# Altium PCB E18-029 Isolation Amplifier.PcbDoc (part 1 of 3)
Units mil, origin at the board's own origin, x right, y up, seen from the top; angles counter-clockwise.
Board outline 5740 x 5970 mil, 4 copper layers (Component Side, V+, V-, Ground), stack 33.234 mil thick; 359 components, 170 nets, 952 pads, 232 vias.
Unrouted connection lines stored in the file: 60.
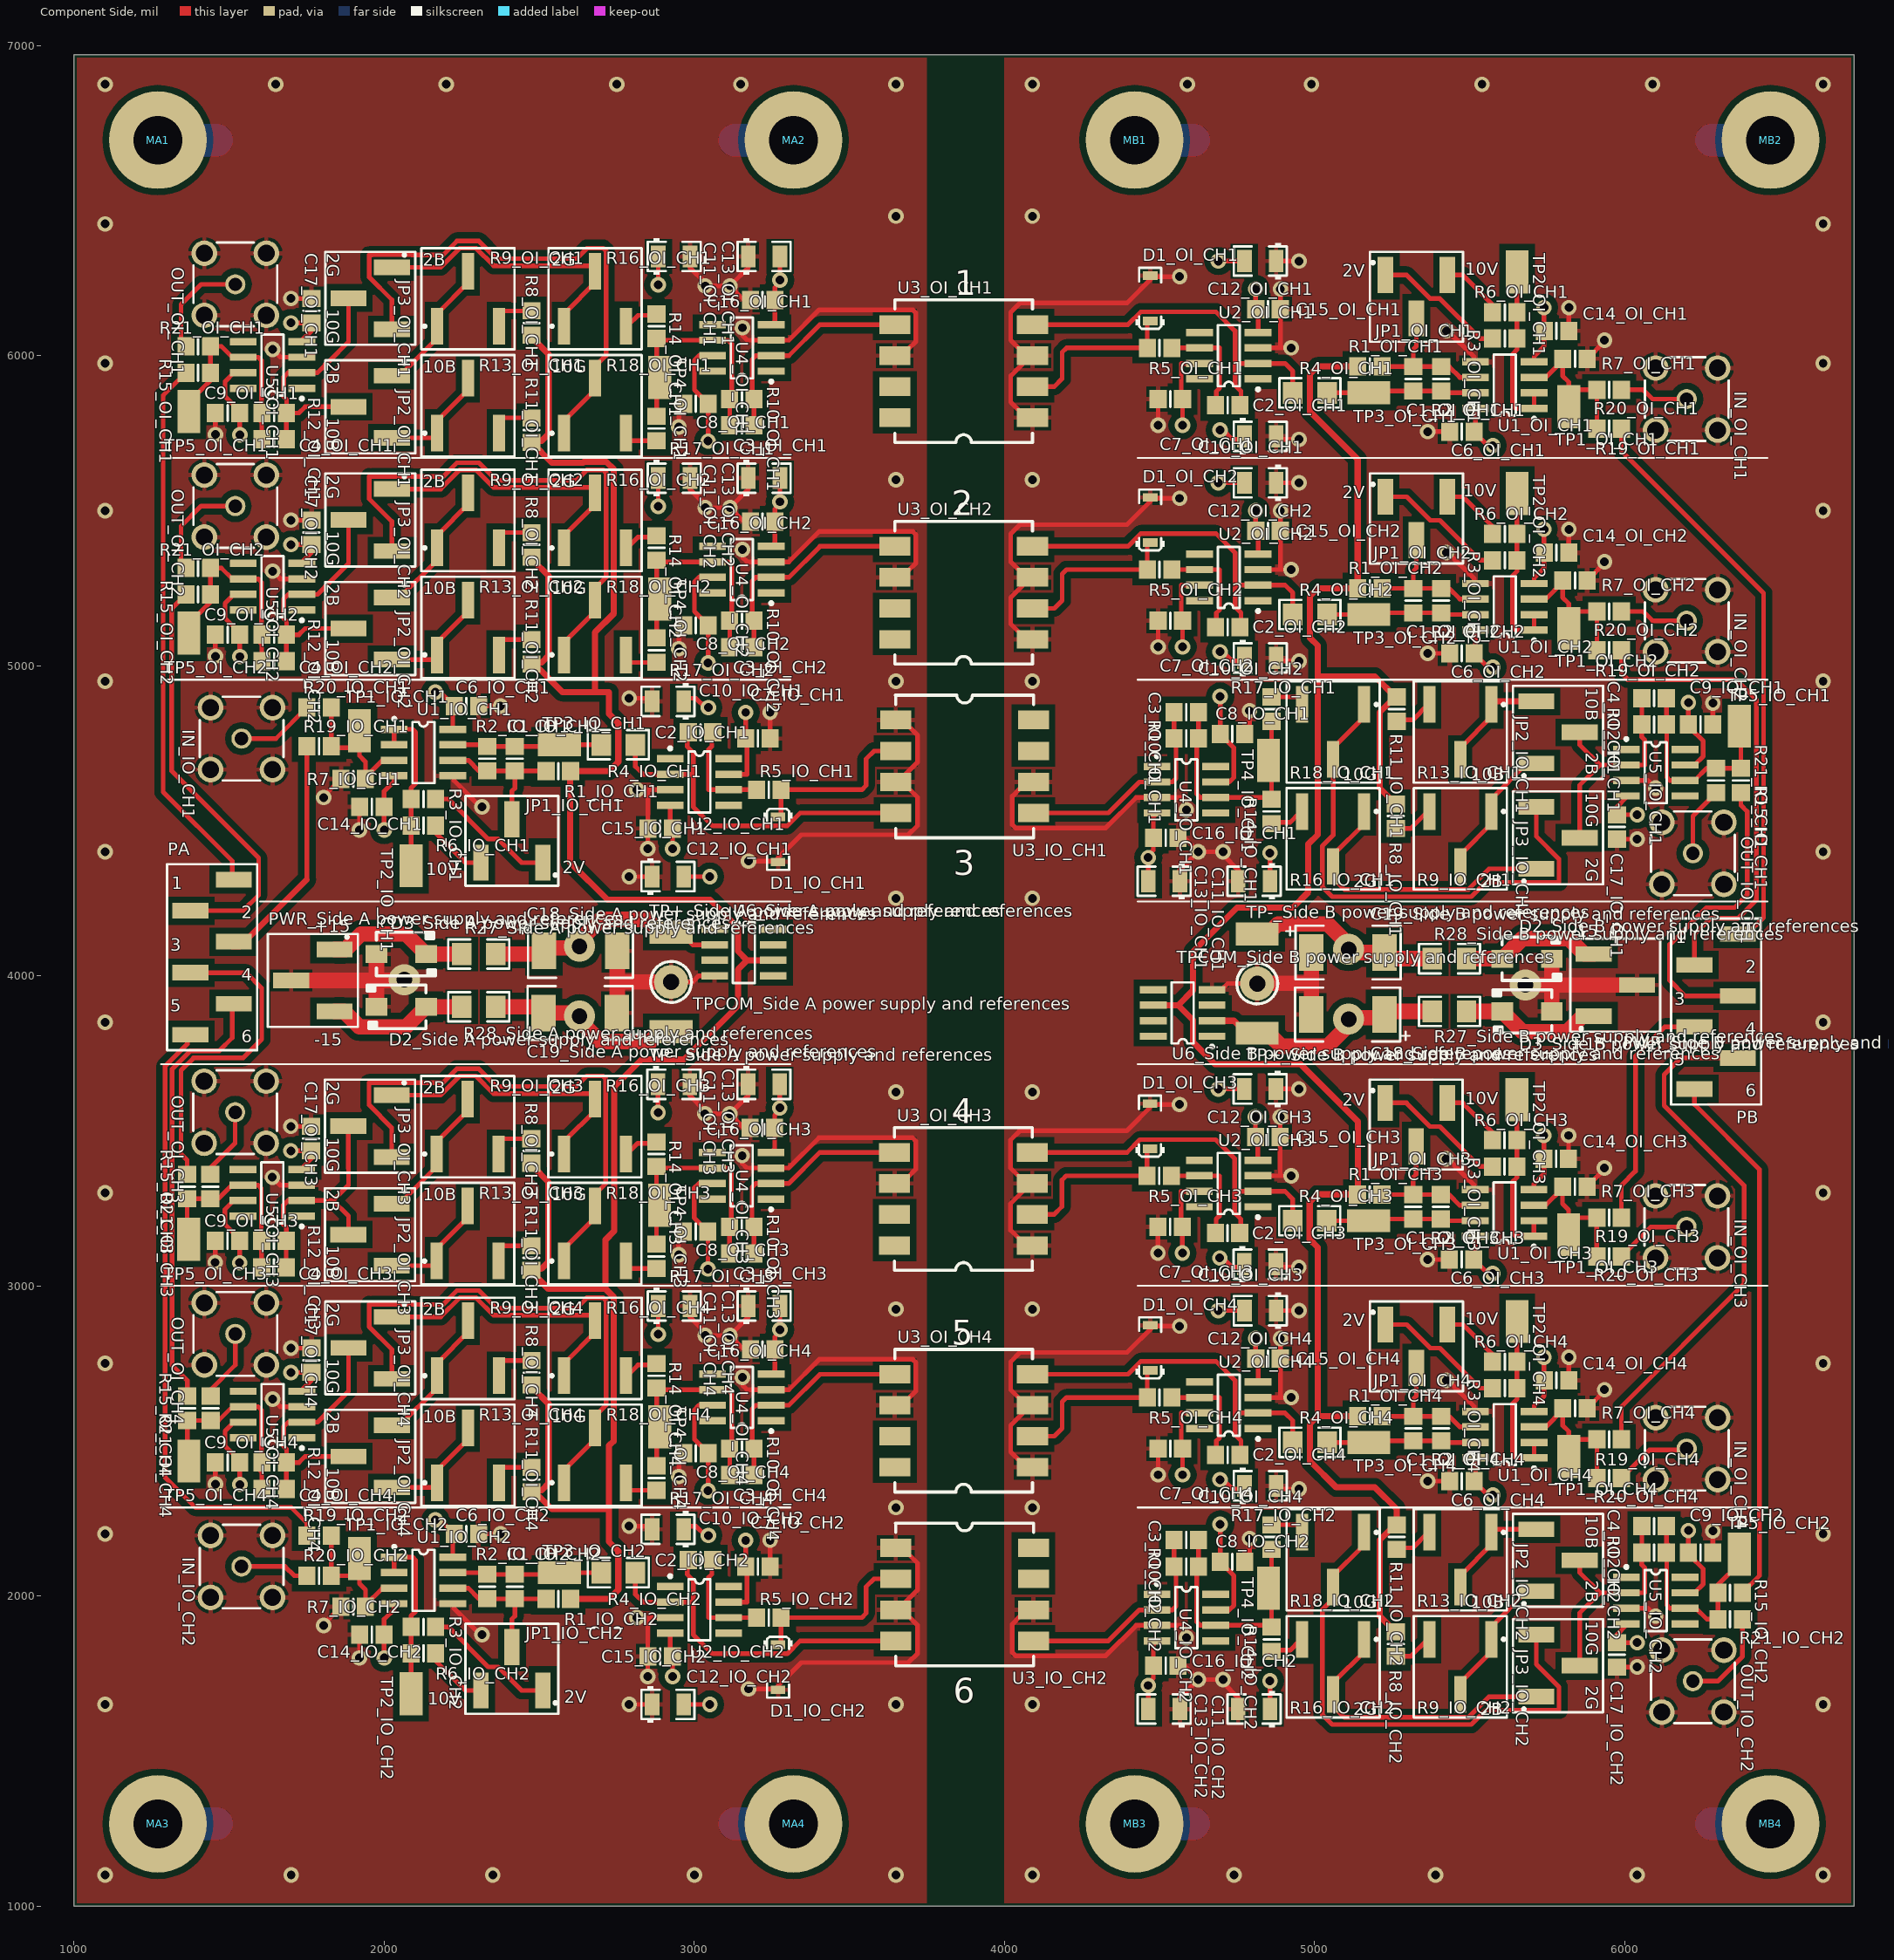
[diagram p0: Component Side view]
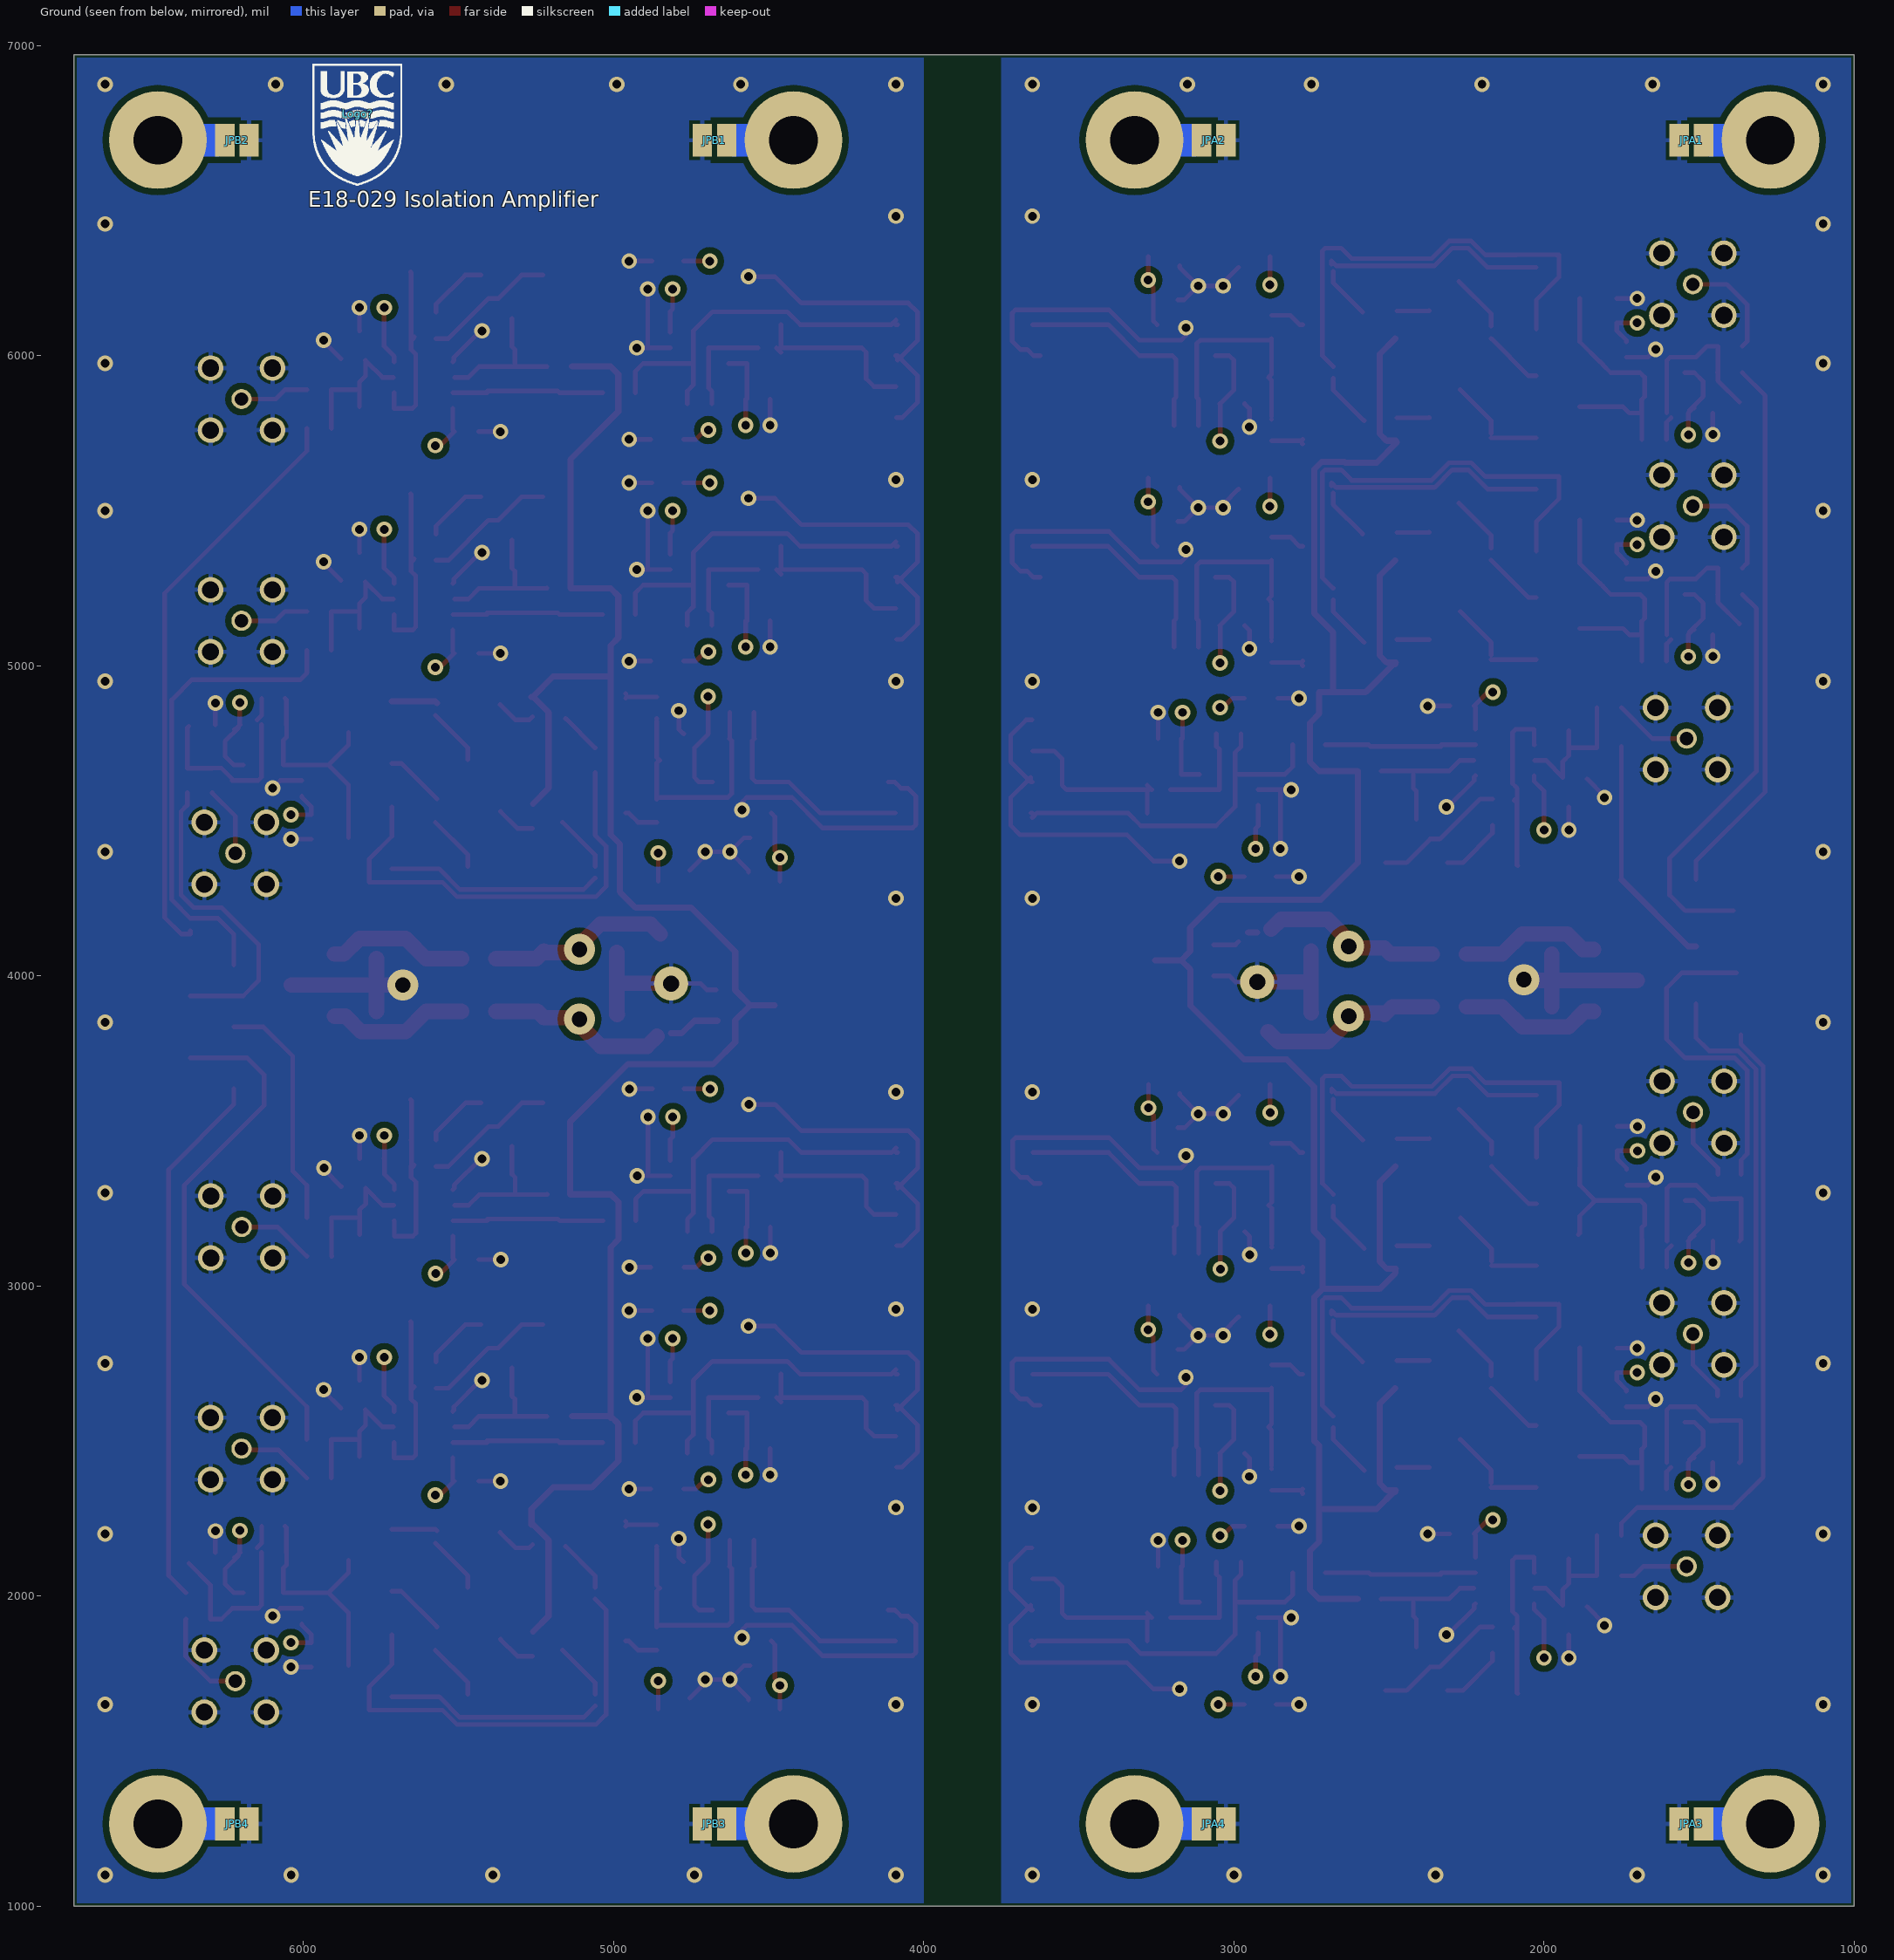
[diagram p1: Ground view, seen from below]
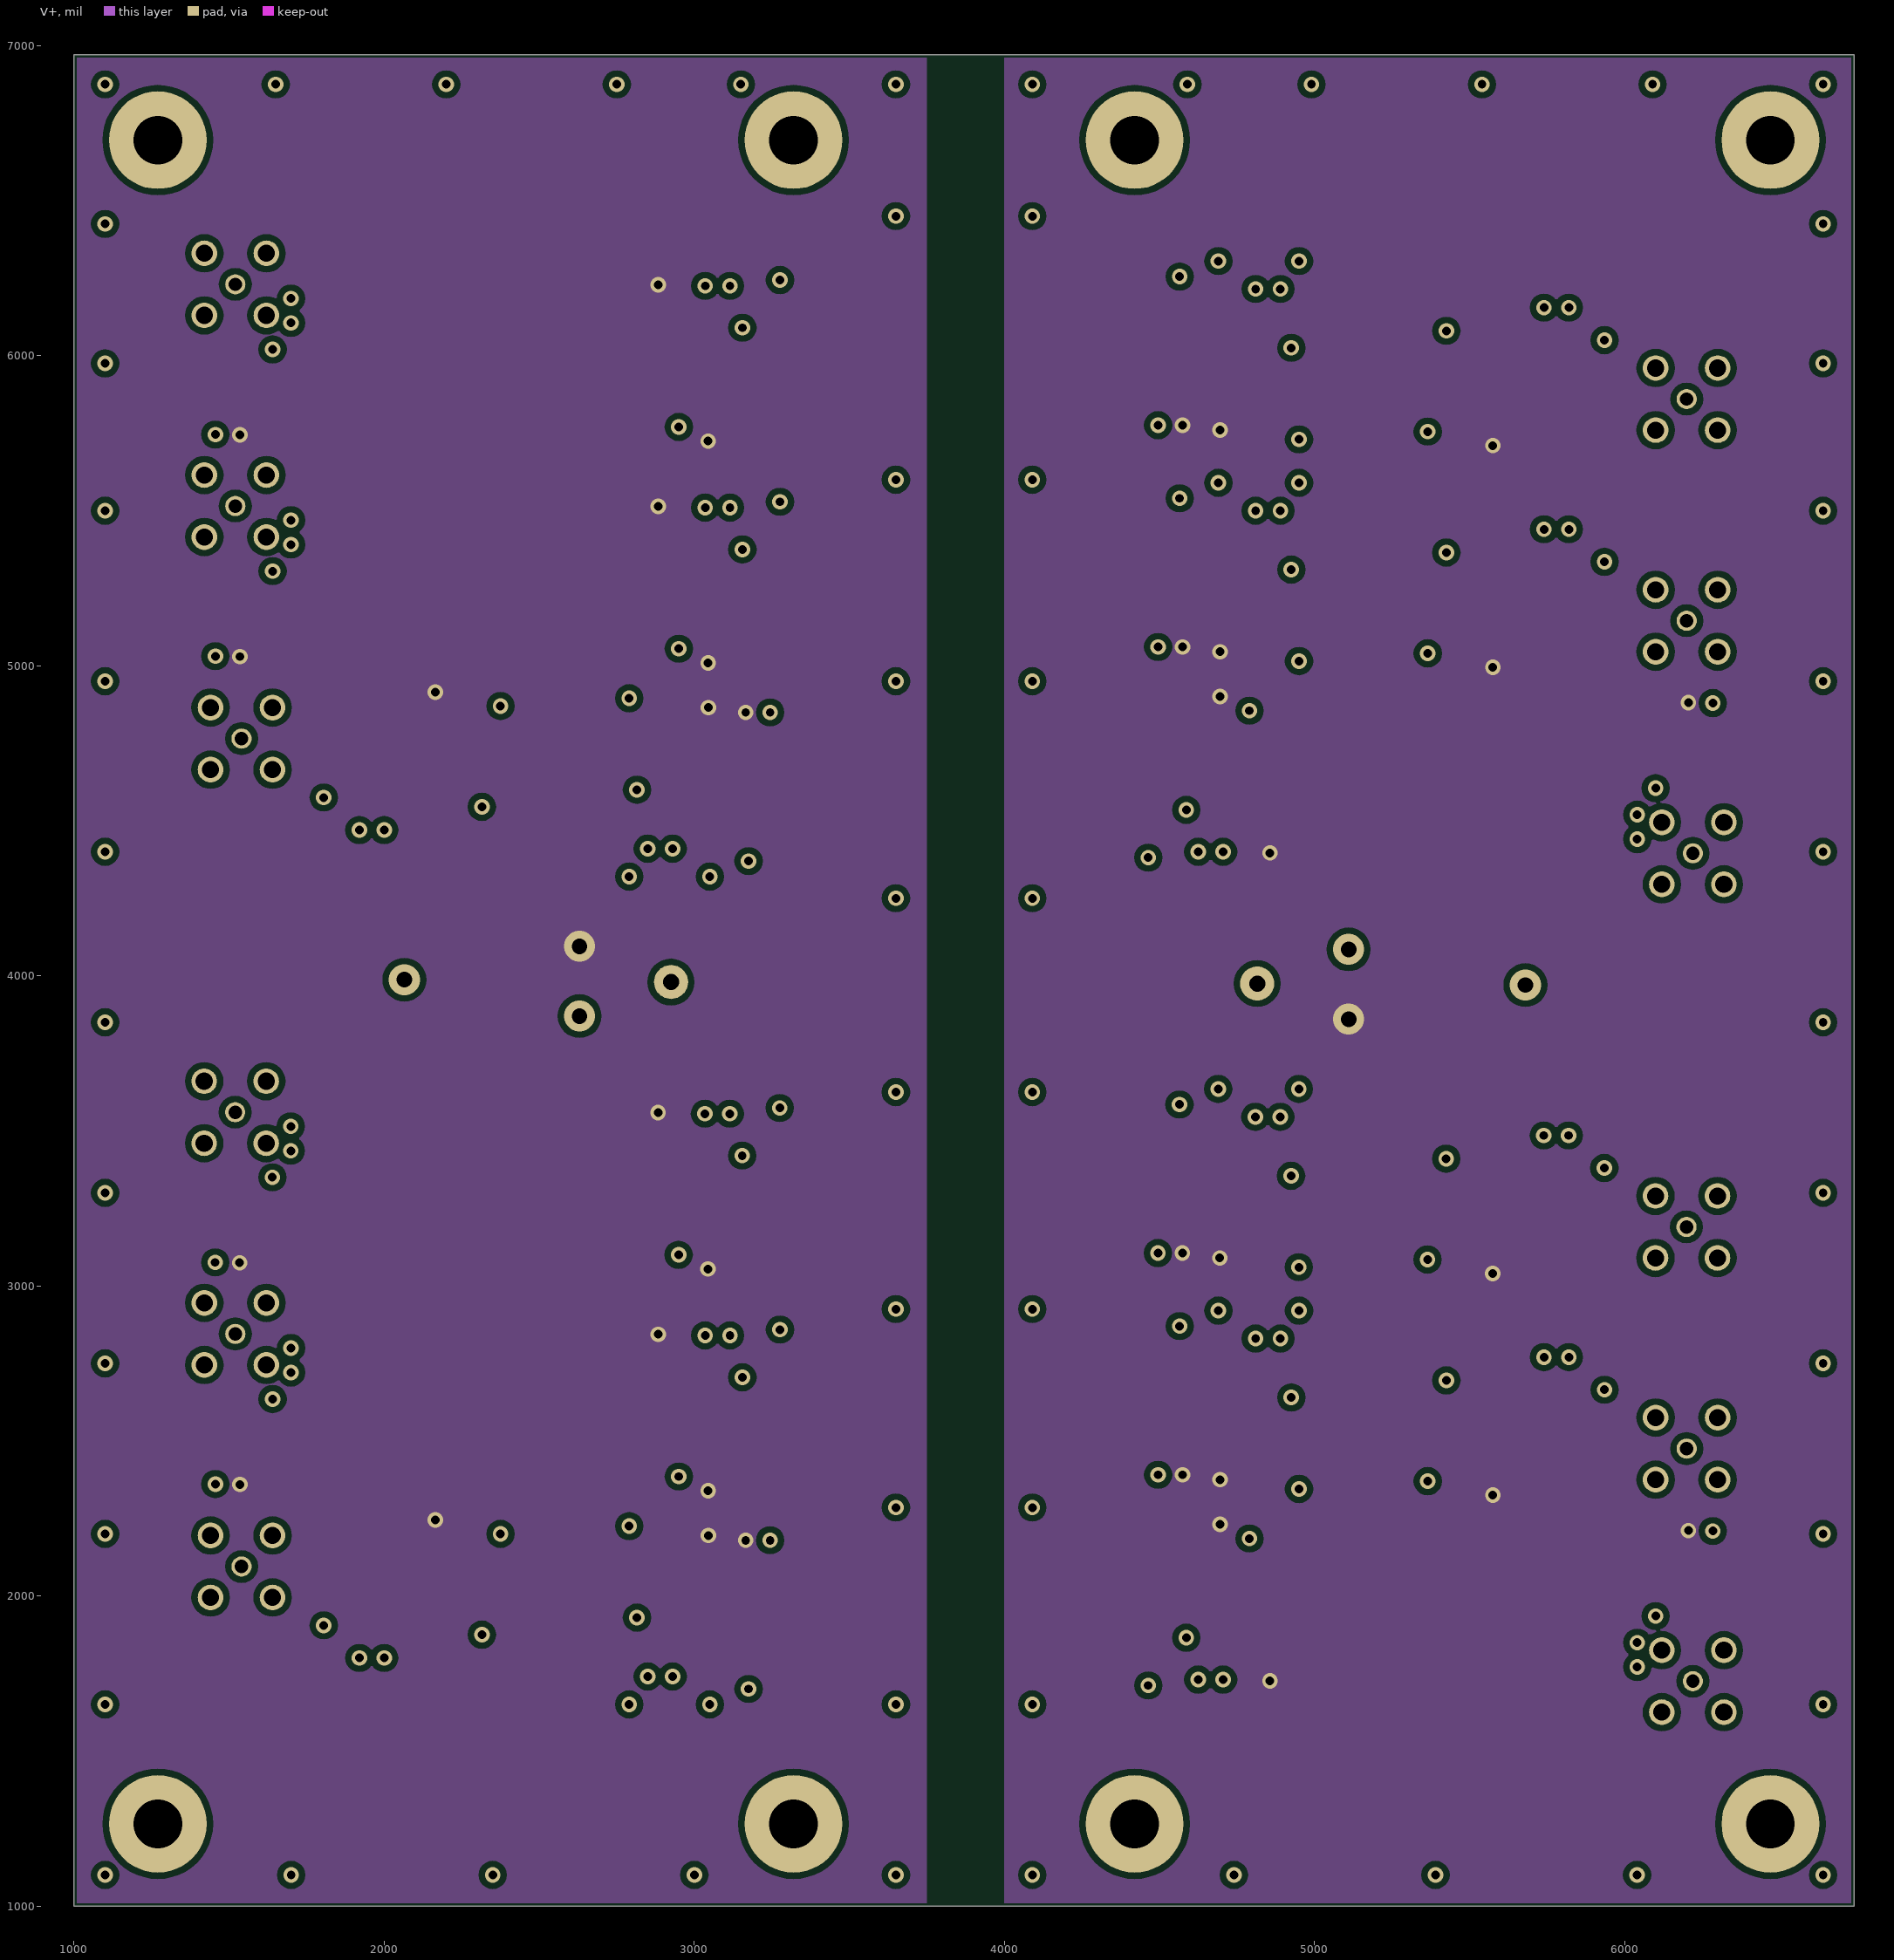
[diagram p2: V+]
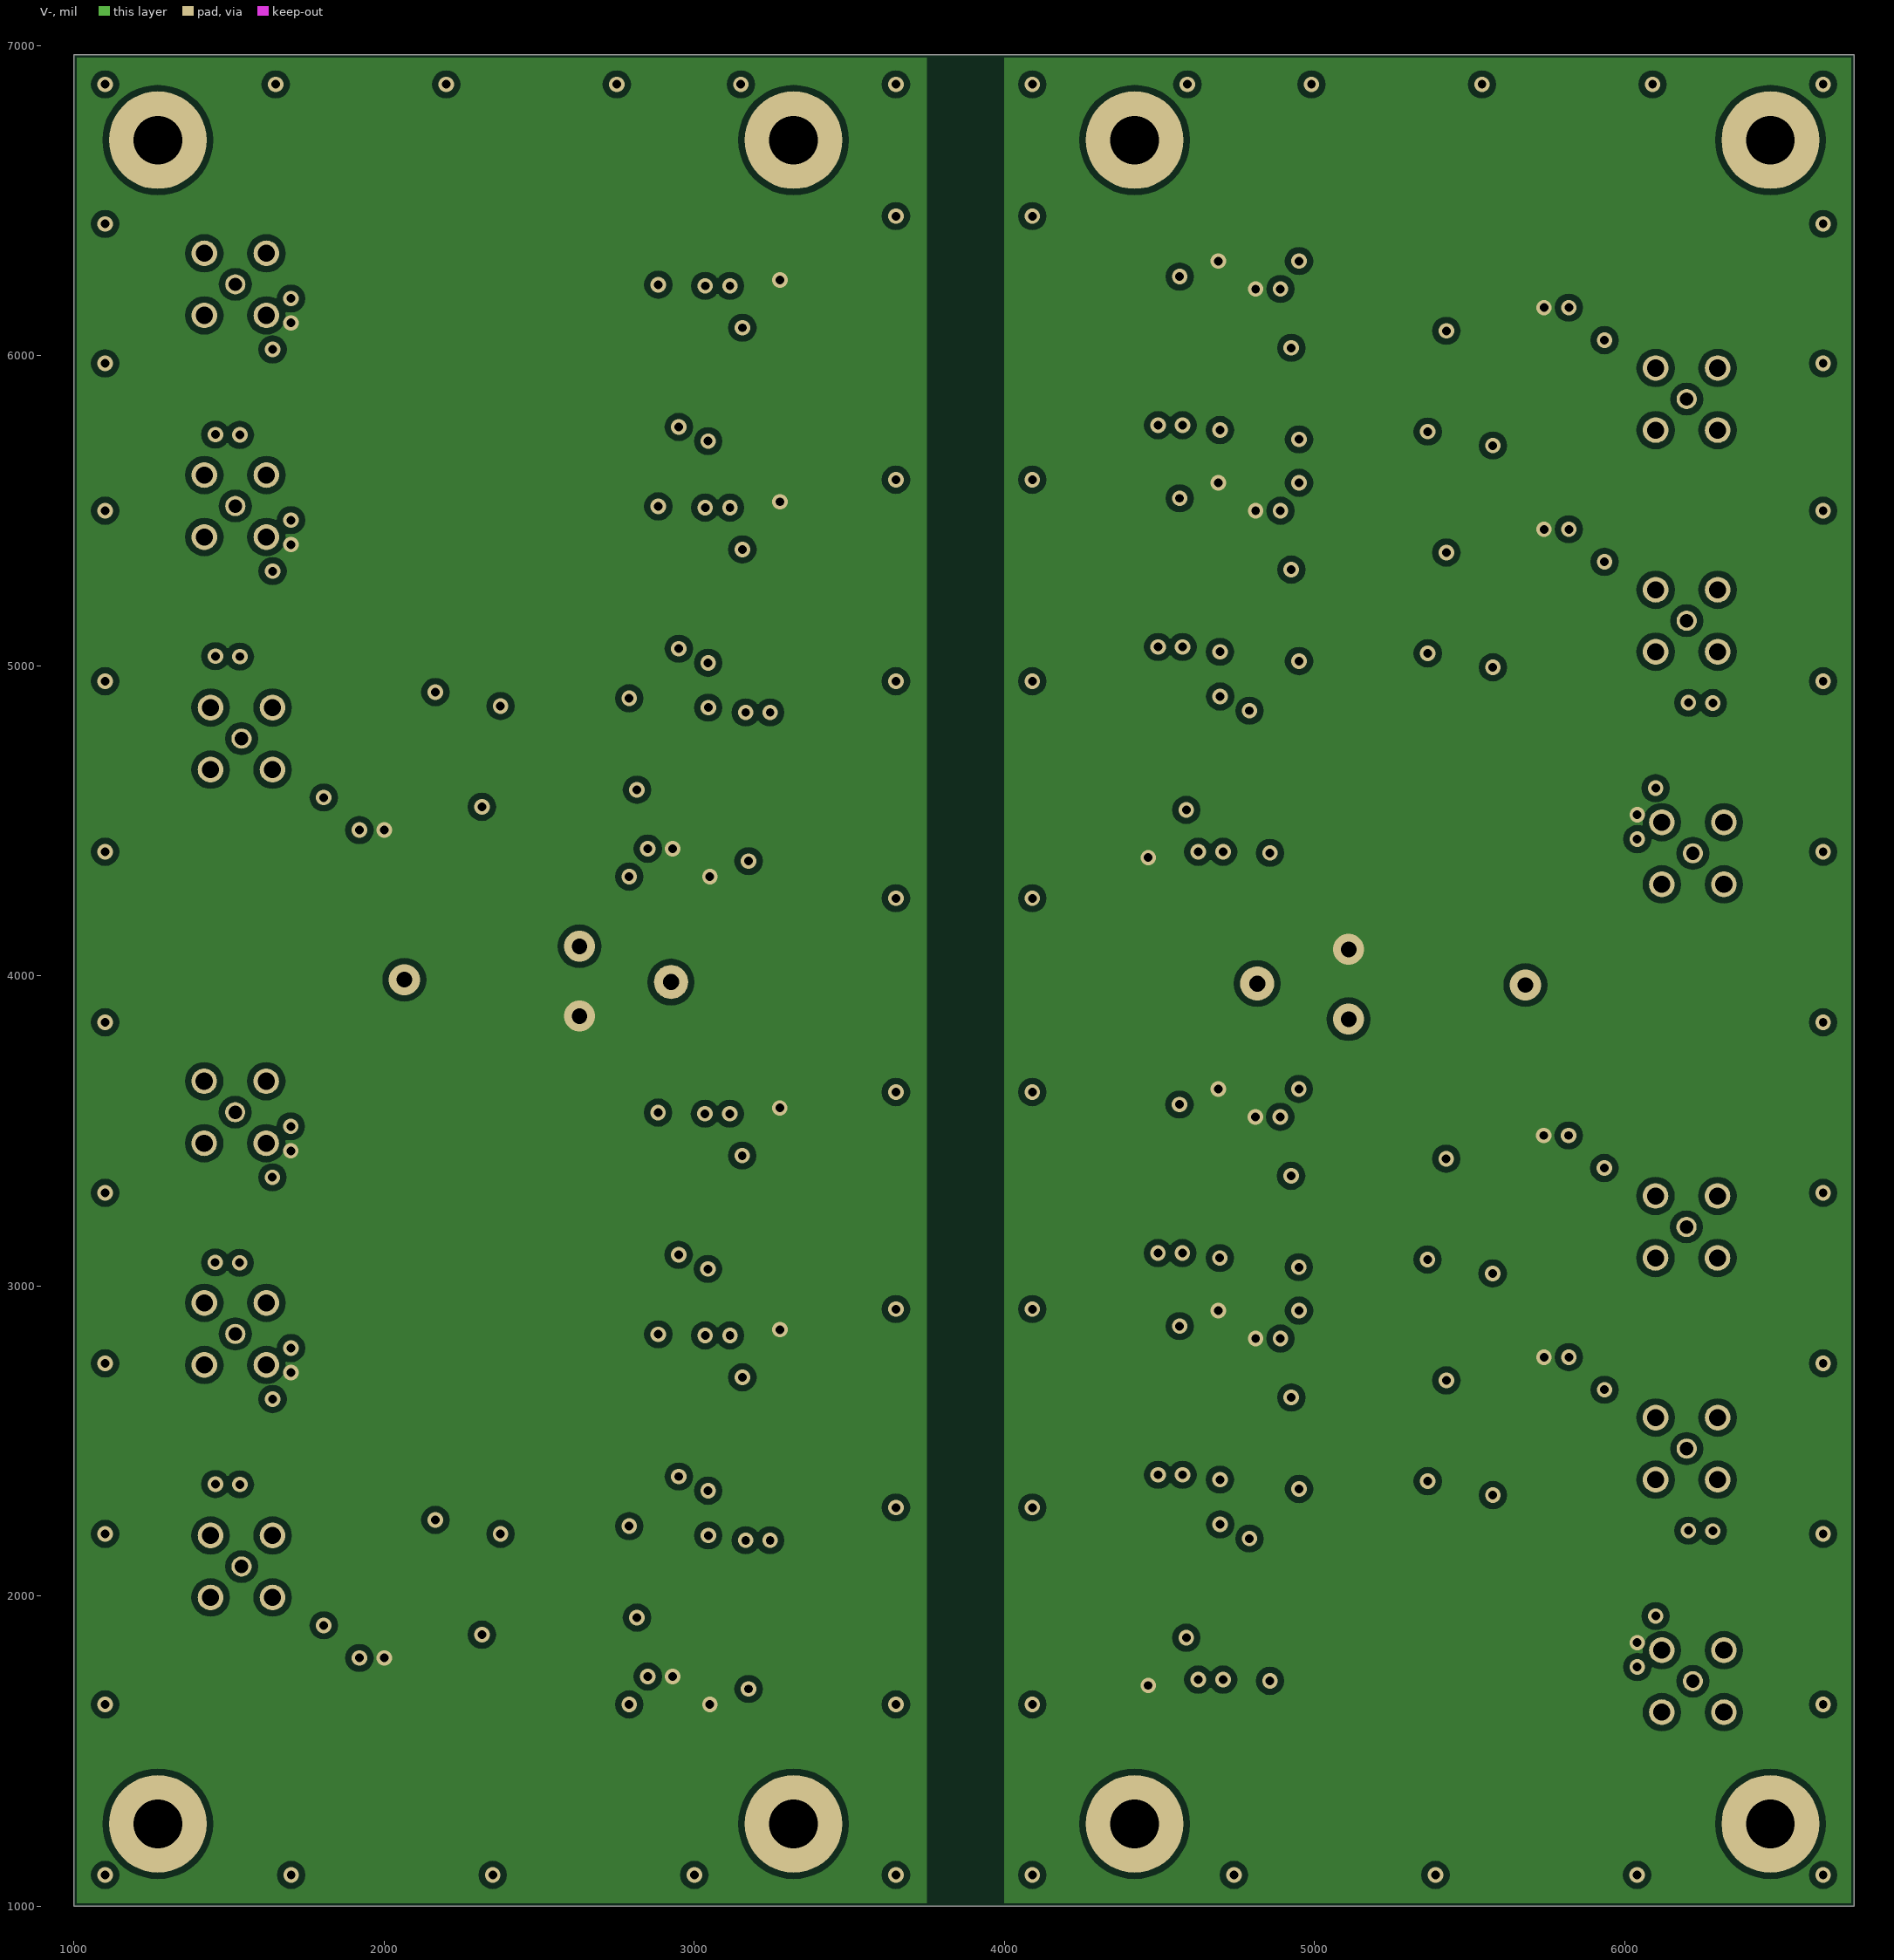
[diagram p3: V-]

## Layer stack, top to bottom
Top Solder: solder mask 0.4, Solder Resist, Dk 3.5
Component Side: signal copper 1.4
Dielectric 1: core 12.6, FR-4, Dk 4.8
V+: signal copper 1.417
Dielectric 4: prepreg 5, Dk 4.2
V-: signal copper 1.417
Dielectric 3: core 10, Dk 4.2
Ground: signal copper 1.4
Bottom Solder: solder mask 0.4, Solder Resist, Dk 3.5

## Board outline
1000,1000 1000,6970 6740,6970 6740,1000

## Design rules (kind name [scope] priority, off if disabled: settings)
AcuteAngle [All] p1: minimum=3.00000000000000E+0001 checktracksonly=FALSE
Clearance Polygon_Pour [InPolygon] p1: gap=20 ignorepadtopadclearanceinfootprint=FALSE except(0: Arc-Hole Track-Hole SMDPad-Hole THPad-Hole Via-Hole Fill-Hole Poly-Hole Region-Hole Text-Hole)
Clearance [All] p2: gap=8 ignorepadtopadclearanceinfootprint=FALSE except(0: Arc-Hole Track-Hole SMDPad-Hole THPad-Hole Via-Hole Fill-Hole Poly-Hole Region-Hole Text-Hole)
HoleSize [All] p1: absolutevalues=TRUE maxlimit=250 minlimit=20 maxpercent=80.000 minpercent=20.000
MinimumAnnularRing [All] p1: minimumring=10
MinimumSolderMaskSliver [All] p1: minsoldermaskwidth=2
MinimumSolderMaskSliver SilkscreenOverComponentPads [All] p2: minsoldermaskwidth=10
PolygonConnect PolygonConnect_1 [All vs IsNamedPolygon('GND_L01_P023') or IsNamedPolygon('GND_L02_P022') or IsNamedPolygon('GND_L03_P021') or IsNamedPolygon('GND_L04_P019')] p1: connectstyle=Direct reliefconductorwidth=10 reliefentries=4 polygonreliefangle="90 Angle" airgapwidth=10
PolygonConnect PolygonViaConnect [IsVia] p2: connectstyle=Direct reliefconductorwidth=15 reliefentries=4 polygonreliefangle="45 Angle" airgapwidth=10
PolygonConnect [All] p3: connectstyle=Relief reliefconductorwidth=15 reliefentries=4 polygonreliefangle="90 Angle" airgapwidth=10
RoomDefinition "E18-029 Isolation Amplifier Top" [InComponentClass('E18-029 Isolation Amplifier Top')] p1: confinementstyle=ConfineOut formatcopy=TRUE lockcomponents=FALSE outline 0,0 645,0 645,320 0,320
RoomDefinition "Side B power supply and references" [InComponentClass('Side B power supply and references')] p2: confinementstyle=ConfineIn formatcopy=TRUE lockcomponents=FALSE outline 4420,3715 6125,3715 6125,4240 4420,4240
RoomDefinition "Side A power supply and references" [InComponentClass('Side A power supply and references')] p3: confinementstyle=ConfineIn formatcopy=TRUE lockcomponents=FALSE outline 3320,4240 1615,4240 1615,3715 3320,3715
RoomDefinition OI_CH4 [InComponentClass('OI_CH4')] p4: confinementstyle=ConfineIn formatcopy=TRUE lockcomponents=FALSE outline 6435,3000 1270,3000 1270,2285 6435,2285
RoomDefinition OI_CH3 [InComponentClass('OI_CH3')] p5: confinementstyle=ConfineIn formatcopy=TRUE lockcomponents=FALSE outline 6434.37,3715 1269.37,3715 1269.37,3000 6434.37,3000
RoomDefinition OI_CH2 [InComponentClass('OI_CH2')] p6: confinementstyle=ConfineIn formatcopy=TRUE lockcomponents=FALSE outline 6435,5670 1270,5670 1270,4955 6435,4955
RoomDefinition OI_CH1 [InComponentClass('OI_CH1')] p7: confinementstyle=ConfineIn formatcopy=TRUE lockcomponents=FALSE outline 6435,6385 1270,6385 1270,5670 6435,5670
RoomDefinition IO_CH2 [InComponentClass('IO_CH2')] p8: confinementstyle=ConfineIn formatcopy=TRUE lockcomponents=FALSE outline 1305,1570 6470,1570 6470,2285 1305,2285
RoomDefinition IO_CH1 [InComponentClass('IO_CH1')] p9: confinementstyle=ConfineIn formatcopy=TRUE lockcomponents=FALSE outline 1305,4240 6470,4240 6470,4955 1305,4955
RoutingVias [All] p1: holewidth=28 width=50 viastyle="Through Hole" minholewidth=28 minwidth=50 maxholewidth=28 maxwidth=50
SilkToSilkClearance [All] p1: silktosilkclearance=2
SilkToSolderMaskClearance [IsPad] p1: minsilkscreentomaskgap=5.9 clearancetoexposedcopper=TRUE
SolderMaskExpansion [All] p1: expansion=4 istentingtop=FALSE
Width [All] p1: maxlimit=105 minlimit=8 preferedwidth=20 toplayer_maxwidth=100 midlayer1_minwidth=10 midlayer1_maxwidth=100 midlayer2_minwidth=10 midlayer2_maxwidth=100 minimp=50.000000 maximp=50.000000 favimp=50.000000
26 further rules are at their usual default settings.

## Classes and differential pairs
channel class "E18-029 Power supply and references": "Side A power supply and references" "Side B power supply and references"
channel class "E18-029 Channel": IO_CH1 IO_CH2 OI_CH1 OI_CH2 OI_CH3 OI_CH4
component class "E18-029 Isolation Amplifier Top": JPA1 JPA2 JPA3 JPA4 JPB1 JPB2 JPB3 JPB4 Logo? MA1 MA2 MA3 MA4 MB1 MB2 MB3 MB4 PA PB
component class "Side B power supply and references": "C18_Side B power supply and references" "C19_Side B power supply and references" "D2_Side B power supply and references" "D3_Side B power supply and references" "PWR_Side B power supply and references" "R27_Side B power supply and references" "R28_Side B power supply and references" "TP+_Side B power supply and references" "TP-_Side B power supply and references" "TPCOM_Side B power supply and references" "U6_Side B power supply and references"
component class "Side A power supply and references": "C18_Side A power supply and references" "C19_Side A power supply and references" "D2_Side A power supply and references" "D3_Side A power supply and references" "PWR_Side A power supply and references" "R27_Side A power supply and references" "R28_Side A power supply and references" "TP+_Side A power supply and references" "TP-_Side A power supply and references" "TPCOM_Side A power supply and references" "U6_Side A power supply and references"
component class OI_CH4: C1_OI_CH4 C2_OI_CH4 C3_OI_CH4 C4_OI_CH4 C6_OI_CH4 C7_OI_CH4 C8_OI_CH4 C9_OI_CH4 C10_OI_CH4 C11_OI_CH4 C12_OI_CH4 C13_OI_CH4 C14_OI_CH4 C15_OI_CH4 C16_OI_CH4 C17_OI_CH4 D1_OI_CH4 IN_OI_CH4 JP1_OI_CH4 JP2_OI_CH4 JP3_OI_CH4 OUT_OI_CH4 R1_OI_CH4 R2_OI_CH4 R3_OI_CH4 R4_OI_CH4 R5_OI_CH4 R6_OI_CH4 R7_OI_CH4 R8_OI_CH4 R9_OI_CH4 R10_OI_CH4 R11_OI_CH4 R12_OI_CH4 R13_OI_CH4 R14_OI_CH4 R15_OI_CH4 R16_OI_CH4 R17_OI_CH4 R18_OI_CH4 R19_OI_CH4 R20_OI_CH4 R21_OI_CH4 TP1_OI_CH4 TP2_OI_CH4 TP3_OI_CH4 TP4_OI_CH4 TP5_OI_CH4 U1_OI_CH4 U2_OI_CH4 U3_OI_CH4 U4_OI_CH4 U5_OI_CH4
component class OI_CH3: C1_OI_CH3 C2_OI_CH3 C3_OI_CH3 C4_OI_CH3 C6_OI_CH3 C7_OI_CH3 C8_OI_CH3 C9_OI_CH3 C10_OI_CH3 C11_OI_CH3 C12_OI_CH3 C13_OI_CH3 C14_OI_CH3 C15_OI_CH3 C16_OI_CH3 C17_OI_CH3 D1_OI_CH3 IN_OI_CH3 JP1_OI_CH3 JP2_OI_CH3 JP3_OI_CH3 OUT_OI_CH3 R1_OI_CH3 R2_OI_CH3 R3_OI_CH3 R4_OI_CH3 R5_OI_CH3 R6_OI_CH3 R7_OI_CH3 R8_OI_CH3 R9_OI_CH3 R10_OI_CH3 R11_OI_CH3 R12_OI_CH3 R13_OI_CH3 R14_OI_CH3 R15_OI_CH3 R16_OI_CH3 R17_OI_CH3 R18_OI_CH3 R19_OI_CH3 R20_OI_CH3 R21_OI_CH3 TP1_OI_CH3 TP2_OI_CH3 TP3_OI_CH3 TP4_OI_CH3 TP5_OI_CH3 U1_OI_CH3 U2_OI_CH3 U3_OI_CH3 U4_OI_CH3 U5_OI_CH3
component class OI_CH2: C1_OI_CH2 C2_OI_CH2 C3_OI_CH2 C4_OI_CH2 C6_OI_CH2 C7_OI_CH2 C8_OI_CH2 C9_OI_CH2 C10_OI_CH2 C11_OI_CH2 C12_OI_CH2 C13_OI_CH2 C14_OI_CH2 C15_OI_CH2 C16_OI_CH2 C17_OI_CH2 D1_OI_CH2 IN_OI_CH2 JP1_OI_CH2 JP2_OI_CH2 JP3_OI_CH2 OUT_OI_CH2 R1_OI_CH2 R2_OI_CH2 R3_OI_CH2 R4_OI_CH2 R5_OI_CH2 R6_OI_CH2 R7_OI_CH2 R8_OI_CH2 R9_OI_CH2 R10_OI_CH2 R11_OI_CH2 R12_OI_CH2 R13_OI_CH2 R14_OI_CH2 R15_OI_CH2 R16_OI_CH2 R17_OI_CH2 R18_OI_CH2 R19_OI_CH2 R20_OI_CH2 R21_OI_CH2 TP1_OI_CH2 TP2_OI_CH2 TP3_OI_CH2 TP4_OI_CH2 TP5_OI_CH2 U1_OI_CH2 U2_OI_CH2 U3_OI_CH2 U4_OI_CH2 U5_OI_CH2
component class OI_CH1: C1_OI_CH1 C2_OI_CH1 C3_OI_CH1 C4_OI_CH1 C6_OI_CH1 C7_OI_CH1 C8_OI_CH1 C9_OI_CH1 C10_OI_CH1 C11_OI_CH1 C12_OI_CH1 C13_OI_CH1 C14_OI_CH1 C15_OI_CH1 C16_OI_CH1 C17_OI_CH1 D1_OI_CH1 IN_OI_CH1 JP1_OI_CH1 JP2_OI_CH1 JP3_OI_CH1 OUT_OI_CH1 R1_OI_CH1 R2_OI_CH1 R3_OI_CH1 R4_OI_CH1 R5_OI_CH1 R6_OI_CH1 R7_OI_CH1 R8_OI_CH1 R9_OI_CH1 R10_OI_CH1 R11_OI_CH1 R12_OI_CH1 R13_OI_CH1 R14_OI_CH1 R15_OI_CH1 R16_OI_CH1 R17_OI_CH1 R18_OI_CH1 R19_OI_CH1 R20_OI_CH1 R21_OI_CH1 TP1_OI_CH1 TP2_OI_CH1 TP3_OI_CH1 TP4_OI_CH1 TP5_OI_CH1 U1_OI_CH1 U2_OI_CH1 U3_OI_CH1 U4_OI_CH1 U5_OI_CH1
component class IO_CH2: C1_IO_CH2 C2_IO_CH2 C3_IO_CH2 C4_IO_CH2 C6_IO_CH2 C7_IO_CH2 C8_IO_CH2 C9_IO_CH2 C10_IO_CH2 C11_IO_CH2 C12_IO_CH2 C13_IO_CH2 C14_IO_CH2 C15_IO_CH2 C16_IO_CH2 C17_IO_CH2 D1_IO_CH2 IN_IO_CH2 JP1_IO_CH2 JP2_IO_CH2 JP3_IO_CH2 OUT_IO_CH2 R1_IO_CH2 R2_IO_CH2 R3_IO_CH2 R4_IO_CH2 R5_IO_CH2 R6_IO_CH2 R7_IO_CH2 R8_IO_CH2 R9_IO_CH2 R10_IO_CH2 R11_IO_CH2 R12_IO_CH2 R13_IO_CH2 R14_IO_CH2 R15_IO_CH2 R16_IO_CH2 R17_IO_CH2 R18_IO_CH2 R19_IO_CH2 R20_IO_CH2 R21_IO_CH2 TP1_IO_CH2 TP2_IO_CH2 TP3_IO_CH2 TP4_IO_CH2 TP5_IO_CH2 U1_IO_CH2 U2_IO_CH2 U3_IO_CH2 U4_IO_CH2 U5_IO_CH2
component class IO_CH1: C1_IO_CH1 C2_IO_CH1 C3_IO_CH1 C4_IO_CH1 C6_IO_CH1 C7_IO_CH1 C8_IO_CH1 C9_IO_CH1 C10_IO_CH1 C11_IO_CH1 C12_IO_CH1 C13_IO_CH1 C14_IO_CH1 C15_IO_CH1 C16_IO_CH1 C17_IO_CH1 D1_IO_CH1 IN_IO_CH1 JP1_IO_CH1 JP2_IO_CH1 JP3_IO_CH1 OUT_IO_CH1 R1_IO_CH1 R2_IO_CH1 R3_IO_CH1 R4_IO_CH1 R5_IO_CH1 R6_IO_CH1 R7_IO_CH1 R8_IO_CH1 R9_IO_CH1 R10_IO_CH1 R11_IO_CH1 R12_IO_CH1 R13_IO_CH1 R14_IO_CH1 R15_IO_CH1 R16_IO_CH1 R17_IO_CH1 R18_IO_CH1 R19_IO_CH1 R20_IO_CH1 R21_IO_CH1 TP1_IO_CH1 TP2_IO_CH1 TP3_IO_CH1 TP4_IO_CH1 TP5_IO_CH1 U1_IO_CH1 U2_IO_CH1 U3_IO_CH1 U4_IO_CH1 U5_IO_CH1

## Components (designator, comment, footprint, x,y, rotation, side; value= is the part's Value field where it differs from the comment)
C1_IO_CH1 "10pF" 6-0805_M 2421.54,4700 r270 top (schematic designator C1)
C1_IO_CH2 "10pF" 6-0805_M 2421.54,2030 r270 top (schematic designator C1)
C1_OI_CH1 "10pF" 6-0805_M 5318.46,5925 r90 top (schematic designator C1)
C1_OI_CH2 "10pF" 6-0805_M 5318.46,5210 r90 top (schematic designator C1)
C1_OI_CH3 "10pF" 6-0805_M 5317.83,3255 r90 top (schematic designator C1)
C1_OI_CH4 "10pF" 6-0805_M 5318.46,2540 r90 top (schematic designator C1)
C2_IO_CH1 "10pF" 6-0805_M 3020,4785 r180 top (schematic designator C2)
C2_IO_CH2 "10pF" 6-0805_M 3020,2115 r180 top (schematic designator C2)
C2_OI_CH1 "10pF" 6-0805_M 4720,5840 r0 top (schematic designator C2)
C2_OI_CH2 "10pF" 6-0805_M 4720,5125 r0 top (schematic designator C2)
C2_OI_CH3 "10pF" 6-0805_M 4719.37,3170 r0 top (schematic designator C2)
C2_OI_CH4 "10pF" 6-0805_M 4720,2455 r0 top (schematic designator C2)
C3_IO_CH1 "10pF" 6-0805_M 4586.54,4850 r180 top value=100pF (schematic designator C3)
C3_IO_CH2 "10pF" 6-0805_M 4586.54,2180 r180 top value=100pF (schematic designator C3)
C3_OI_CH1 "10pF" 6-0805_M 3153.46,5775 r0 top value=100pF (schematic designator C3)
C3_OI_CH2 "10pF" 6-0805_M 3153.46,5060 r0 top value=100pF (schematic designator C3)
C3_OI_CH3 "10pF" 6-0805_M 3152.83,3105 r0 top value=100pF (schematic designator C3)
C3_OI_CH4 "10pF" 6-0805_M 3153.46,2390 r0 top value=100pF (schematic designator C3)
C4_IO_CH1 "10pF" 6-0805_M 6095,4895 r180 top (schematic designator C4)
C4_IO_CH2 "10pF" 6-0805_M 6095,2225 r180 top (schematic designator C4)
C4_OI_CH1 "10pF" 6-0805_M 1645,5730 r0 top (schematic designator C4)
C4_OI_CH2 "10pF" 6-0805_M 1645,5015 r0 top (schematic designator C4)
C4_OI_CH3 "10pF" 6-0805_M 1644.37,3060 r0 top (schematic designator C4)
C4_OI_CH4 "10pF" 6-0805_M 1645,2345 r0 top (schematic designator C4)
C6_IO_CH1 "100nF" 6-0805_M 2265,4870 r180 top (schematic designator C6)
C6_IO_CH2 "100nF" 6-0805_M 2265,2200 r180 top (schematic designator C6)
C6_OI_CH1 "100nF" 6-0805_M 5475,5755 r0 top (schematic designator C6)
C6_OI_CH2 "100nF" 6-0805_M 5475,5040 r0 top (schematic designator C6)
C6_OI_CH3 "100nF" 6-0805_M 5474.37,3085 r0 top (schematic designator C6)
C6_OI_CH4 "100nF" 6-0805_M 5475,2370 r0 top (schematic designator C6)
C7_IO_CH1 "100nF" 6-0805_M 3205,4765 r180 top (schematic designator C7)
C7_IO_CH2 "100nF" 6-0805_M 3205,2095 r180 top (schematic designator C7)
C7_OI_CH1 "100nF" 6-0805_M 4535,5860 r0 top (schematic designator C7)
C7_OI_CH2 "100nF" 6-0805_M 4535,5145 r0 top (schematic designator C7)
C7_OI_CH3 "100nF" 6-0805_M 4534.37,3190 r0 top (schematic designator C7)
C7_OI_CH4 "100nF" 6-0805_M 4535,2475 r0 top (schematic designator C7)
C8_IO_CH1 "100nF" 6-0805_M 4735,4780 r180 top (schematic designator C8)
C8_IO_CH2 "100nF" 6-0805_M 4735,2110 r180 top (schematic designator C8)
C8_OI_CH1 "100nF" 6-0805_M 3005,5845 r0 top (schematic designator C8)
C8_OI_CH2 "100nF" 6-0805_M 3005,5130 r0 top (schematic designator C8)
C8_OI_CH3 "100nF" 6-0805_M 3004.37,3175 r0 top (schematic designator C8)
C8_OI_CH4 "100nF" 6-0805_M 3005,2460 r0 top (schematic designator C8)
C9_IO_CH1 "100nF" 6-0805_M 6245,4810 r180 top (schematic designator C9)
C9_IO_CH2 "100nF" 6-0805_M 6245,2140 r180 top (schematic designator C9)
C9_OI_CH1 "100nF" 6-0805_M 1495,5815 r0 top (schematic designator C9)
C9_OI_CH2 "100nF" 6-0805_M 1495,5100 r0 top (schematic designator C9)
C9_OI_CH3 "100nF" 6-0805_M 1494.37,3145 r0 top (schematic designator C9)
C9_OI_CH4 "100nF" 6-0805_M 1495,2430 r0 top (schematic designator C9)
C10_IO_CH1 "Tant Poly 10uF" CC3216 2915,4885 r180 top value=10uF (schematic designator C10)
C10_IO_CH2 "Tant Poly 10uF" CC3216 2915,2215 r180 top value=10uF (schematic designator C10)
C10_OI_CH1 "Tant Poly 10uF" CC3216 4825,5740 r0 top value=10uF (schematic designator C10)
C10_OI_CH2 "Tant Poly 10uF" CC3216 4825,5025 r0 top value=10uF (schematic designator C10)
C10_OI_CH3 "Tant Poly 10uF" CC3216 4824.37,3070 r0 top value=10uF (schematic designator C10)
C10_OI_CH4 "Tant Poly 10uF" CC3216 4825,2355 r0 top value=10uF (schematic designator C10)
C11_IO_CH1 "Tant Poly 10uF" CC3216 4805,4305 r180 top value=10uF (schematic designator C11)
C11_IO_CH2 "Tant Poly 10uF" CC3216 4805,1635 r180 top value=10uF (schematic designator C11)
C11_OI_CH1 "Tant Poly 10uF" CC3216 2935,6320 r0 top value=10uF (schematic designator C11)
C11_OI_CH2 "Tant Poly 10uF" CC3216 2935,5605 r0 top value=10uF (schematic designator C11)
C11_OI_CH3 "Tant Poly 10uF" CC3216 2934.37,3650 r0 top value=10uF (schematic designator C11)
C11_OI_CH4 "Tant Poly 10uF" CC3216 2935,2935 r0 top value=10uF (schematic designator C11)
C12_IO_CH1 "Tant Poly 10uF" CC3216 2915,4320 r0 top value=10uF (schematic designator C12)
C12_IO_CH2 "Tant Poly 10uF" CC3216 2915,1650 r0 top value=10uF (schematic designator C12)
C12_OI_CH1 "Tant Poly 10uF" CC3216 4825,6305 r180 top value=10uF (schematic designator C12)
C12_OI_CH2 "Tant Poly 10uF" CC3216 4825,5590 r180 top value=10uF (schematic designator C12)
C12_OI_CH3 "Tant Poly 10uF" CC3216 4824.37,3635 r180 top value=10uF (schematic designator C12)
C12_OI_CH4 "Tant Poly 10uF" CC3216 4825,2920 r180 top value=10uF (schematic designator C12)
C13_IO_CH1 "Tant Poly 10uF" CC3216 4515,4305 r180 top value=10uF (schematic designator C13)
C13_IO_CH2 "Tant Poly 10uF" CC3216 4515,1635 r180 top value=10uF (schematic designator C13)
C13_OI_CH1 "Tant Poly 10uF" CC3216 3225,6320 r0 top value=10uF (schematic designator C13)
C13_OI_CH2 "Tant Poly 10uF" CC3216 3225,5605 r0 top value=10uF (schematic designator C13)
C13_OI_CH3 "Tant Poly 10uF" CC3216 3224.37,3650 r0 top value=10uF (schematic designator C13)
C13_OI_CH4 "Tant Poly 10uF" CC3216 3225,2935 r0 top value=10uF (schematic designator C13)
C14_IO_CH1 "100nF" 6-0805_M 1960,4545 r0 top (schematic designator C14)
C14_IO_CH2 "100nF" 6-0805_M 1960,1875 r0 top (schematic designator C14)
C14_OI_CH1 "100nF" 6-0805_M 5780,6080 r180 top (schematic designator C14)
C14_OI_CH2 "100nF" 6-0805_M 5780,5365 r180 top (schematic designator C14)
C14_OI_CH3 "100nF" 6-0805_M 5779.37,3410 r180 top (schematic designator C14)
C14_OI_CH4 "100nF" 6-0805_M 5780,2695 r180 top (schematic designator C14)
C15_IO_CH1 "100nF" 6-0805_M 2890,4475 r0 top (schematic designator C15)
C15_IO_CH2 "100nF" 6-0805_M 2890,1805 r0 top (schematic designator C15)
C15_OI_CH1 "100nF" 6-0805_M 4850,6150 r180 top (schematic designator C15)
C15_OI_CH2 "100nF" 6-0805_M 4850,5435 r180 top (schematic designator C15)
C15_OI_CH3 "100nF" 6-0805_M 4849.37,3480 r180 top (schematic designator C15)
C15_OI_CH4 "100nF" 6-0805_M 4850,2765 r180 top (schematic designator C15)
C16_IO_CH1 "100nF" 6-0805_M 4520,4445 r180 top (schematic designator C16)
C16_IO_CH2 "100nF" 6-0805_M 4520,1775 r180 top (schematic designator C16)
C16_OI_CH1 "100nF" 6-0805_M 3220,6180 r0 top (schematic designator C16)
C16_OI_CH2 "100nF" 6-0805_M 3220,5465 r0 top (schematic designator C16)
C16_OI_CH3 "100nF" 6-0805_M 3219.37,3510 r0 top (schematic designator C16)
C16_OI_CH4 "100nF" 6-0805_M 3220,2795 r0 top (schematic designator C16)
C17_IO_CH1 "100nF" 6-0805_M 5975,4480 r90 top (schematic designator C17)
C17_IO_CH2 "100nF" 6-0805_M 5975,1810 r90 top (schematic designator C17)
C17_OI_CH1 "100nF" 6-0805_M 1765,6145 r270 top (schematic designator C17)
C17_OI_CH2 "100nF" 6-0805_M 1765,5430 r270 top (schematic designator C17)
C17_OI_CH3 "100nF" 6-0805_M 1764.37,3475 r270 top (schematic designator C17)
C17_OI_CH4 "100nF" 6-0805_M 1765,2760 r270 top (schematic designator C17)
"C18_Side A power supply and references" "CAP TANT POLY 100UF 25V 2917" CC7343 2515,4080 r0 top value=100u (schematic designator C18)
"C18_Side B power supply and references" "CAP TANT POLY 100UF 25V 2917" CC7343 5225,3875 r180 top value=100u (schematic designator C18)
"C19_Side A power supply and references" "CAP TANT POLY 100UF 25V 2917" CC7343 2750,3880 r180 top value=100u (schematic designator C19)
"C19_Side B power supply and references" "CAP TANT POLY 100UF 25V 2917" CC7343 4990,4075 r0 top value=100u (schematic designator C19)
D1_IO_CH1 "1N4148W" SOD-123 3270,4440 r90 top (schematic designator D1)
D1_IO_CH2 "1N4148W" SOD-123 3270,1770 r90 top (schematic designator D1)
D1_OI_CH1 "1N4148W" SOD-123 4470,6185 r270 top (schematic designator D1)
D1_OI_CH2 "1N4148W" SOD-123 4470.01,5470 r270 top (schematic designator D1)
D1_OI_CH3 "1N4148W" SOD-123 4469.36,3515 r270 top (schematic designator D1)
D1_OI_CH4 "1N4148W" SOD-123 4470,2800 r270 top (schematic designator D1)
"D2_Side A power supply and references" "SMAZ18-13-F" SMAJ 2055,4070 r0 top (schematic designator D2)
"D2_Side B power supply and references" "SMAZ18-13-F" SMAJ 5685,3885 r180 top (schematic designator D2)
"D3_Side A power supply and references" "SMAZ18-13-F" SMAJ 2055,3900 r180 top (schematic designator D3)
"D3_Side B power supply and references" "SMAZ18-13-F" SMAJ 5685,4055 r0 top (schematic designator D3)
IN_IO_CH1 "SMB Male Vertical Mount" SMB_Male_Vertical 1540,4765 r0 top (schematic designator IN)
IN_IO_CH2 "SMB Male Vertical Mount" SMB_Male_Vertical 1540,2095 r0 top (schematic designator IN)
IN_OI_CH1 "SMB Male Vertical Mount" SMB_Male_Vertical 6200,5860 r180 top (schematic designator IN)
IN_OI_CH2 "SMB Male Vertical Mount" SMB_Male_Vertical 6200,5145 r180 top (schematic designator IN)
IN_OI_CH3 "SMB Male Vertical Mount" SMB_Male_Vertical 6199.37,3190 r180 top (schematic designator IN)
IN_OI_CH4 "SMB Male Vertical Mount" SMB_Male_Vertical 6200,2475 r180 top (schematic designator IN)
JP1_IO_CH1 "JMPR" "HDR1X3 SMD" 2511.54,4365 r180 top (schematic designator JP1)
JP1_IO_CH2 "JMPR" "HDR1X3 SMD" 2511.54,1695 r180 top (schematic designator JP1)
JP1_OI_CH1 "JMPR" "HDR1X3 SMD" 5228.46,6260 r0 top (schematic designator JP1)
JP1_OI_CH2 "JMPR" "HDR1X3 SMD" 5228.46,5545 r0 top (schematic designator JP1)
JP1_OI_CH3 "JMPR" "HDR1X3 SMD" 5227.83,3590 r0 top (schematic designator JP1)
JP1_OI_CH4 "JMPR" "HDR1X3 SMD" 5228.46,2875 r0 top (schematic designator JP1)
JP2_IO_CH1 "JMPR" "HDR1X3 SMD" 5715,4685 r90 top (schematic designator JP2)
JP2_IO_CH2 "JMPR" "HDR1X3 SMD" 5715,2015 r90 top (schematic designator JP2)
JP2_OI_CH1 "JMPR" "HDR1X3 SMD" 2025,5935 r270 top (schematic designator JP2)
JP2_OI_CH2 "JMPR" "HDR1X3 SMD" 2025,5220 r270 top (schematic designator JP2)
JP2_OI_CH3 "JMPR" "HDR1X3 SMD" 2024.37,3265 r270 top (schematic designator JP2)
JP2_OI_CH4 "JMPR" "HDR1X3 SMD" 2025,2550 r270 top (schematic designator JP2)
JP3_IO_CH1 "JMPR" "HDR1X3 SMD" 5715,4345 r90 top (schematic designator JP3)
JP3_IO_CH2 "JMPR" "HDR1X3 SMD" 5715,1675 r90 top (schematic designator JP3)
JP3_OI_CH1 "JMPR" "HDR1X3 SMD" 2025,6285 r270 top (schematic designator JP3)
JP3_OI_CH2 "JMPR" "HDR1X3 SMD" 2025,5570 r270 top (schematic designator JP3)
JP3_OI_CH3 "JMPR" "HDR1X3 SMD" 2024.37,3615 r270 top (schematic designator JP3)
JP3_OI_CH4 "JMPR" "HDR1X3 SMD" 2025,2900 r270 top (schematic designator JP3)
JPA1 "JMPR" "Jumper 1210" 1525,6695 r0 bottom
JPA2 "JMPR" "Jumper 1210" 3065,6695 r180 bottom
JPA3 "JMPR" "Jumper 1210" 1525,1265 r0 bottom
JPA4 "JMPR" "Jumper 1210" 3065,1265 r180 bottom
JPB1 "JMPR" "Jumper 1210" 4675,6695 r0 bottom
JPB2 "JMPR" "Jumper 1210" 6215,6695 r180 bottom
JPB3 "JMPR" "Jumper 1210" 4675,1265 r0 bottom
JPB4 "JMPR" "Jumper 1210" 6215,1265 r180 bottom
Logo? "Use UBC Logo" "UBC Logo" 5825,6780 r180 bottom
MA1 "Pad" "Mtg_Hole_M4 no silk" 1270,6695 r0 top
MA2 "Pad" "Mtg_Hole_M4 no silk" 3320,6695 r0 top
MA3 "Pad" "Mtg_Hole_M4 no silk" 1270,1265 r0 top
MA4 "Pad" "Mtg_Hole_M4 no silk" 3320,1265 r0 top
MB1 "Pad" "Mtg_Hole_M4 no silk" 4420,6695 r0 top
MB2 "Pad" "Mtg_Hole_M4 no silk" 6470,6695 r0 top
MB3 "Pad" "Mtg_Hole_M4 no silk" 4420,1265 r0 top
MB4 "Pad" "Mtg_Hole_M4 no silk" 6470,1265 r0 top
OUT_IO_CH1 "SMB Male Vertical Mount" SMB_Male_Vertical 6220,4395 r0 top (schematic designator OUT)
OUT_IO_CH2 "SMB Male Vertical Mount" SMB_Male_Vertical 6220,1725 r0 top (schematic designator OUT)
OUT_OI_CH1 "SMB Male Vertical Mount" SMB_Male_Vertical 1520,6230 r180 top (schematic designator OUT)
OUT_OI_CH2 "SMB Male Vertical Mount" SMB_Male_Vertical 1520,5515 r180 top (schematic designator OUT)
OUT_OI_CH3 "SMB Male Vertical Mount" SMB_Male_Vertical 1519.37,3560 r180 top (schematic designator OUT)
OUT_OI_CH4 "SMB Male Vertical Mount" SMB_Male_Vertical 1520,2845 r180 top (schematic designator OUT)
PA "HEADER 1X6" "HDR1X6 SMD" 1515,4310 r270 top
PB "HEADER 1X6" "HDR1X6 SMD" 6365,4135 r270 top
"PWR_Side A power supply and references" "JMPR" "HDR1X3 SMD" 1840,4085 r270 top (schematic designator PWR)
"PWR_Side B power supply and references" "JMPR" "HDR1X3 SMD" 5900,3870 r90 top (schematic designator PWR)
R1_IO_CH1 "10k" 6-0805_M 2561.54,4660 r0 top (schematic designator R1)
R1_IO_CH2 "10k" 6-0805_M 2561.54,1990 r0 top (schematic designator R1)
R1_OI_CH1 "10k" 6-0805_M 5178.46,5965 r180 top (schematic designator R1)
R1_OI_CH2 "10k" 6-0805_M 5178.46,5250 r180 top (schematic designator R1)
R1_OI_CH3 "10k" 6-0805_M 5177.83,3295 r180 top (schematic designator R1)
R1_OI_CH4 "10k" 6-0805_M 5178.46,2580 r180 top (schematic designator R1)
R2_IO_CH1 "1k" 6-0805_M 2332.17,4700 r270 top (schematic designator R2)
R2_IO_CH2 "1k" 6-0805_M 2332.17,2030 r270 top (schematic designator R2)
R2_OI_CH1 "1k" 6-0805_M 5407.83,5925 r90 top (schematic designator R2)
R2_OI_CH2 "1k" 6-0805_M 5407.83,5210 r90 top (schematic designator R2)
R2_OI_CH3 "1k" 6-0805_M 5407.2,3255 r90 top (schematic designator R2)
R2_OI_CH4 "1k" 6-0805_M 5407.83,2540 r90 top (schematic designator R2)
R3_IO_CH1 "2k" 6-0805_M 2126.54,4570 r180 top (schematic designator R3)
R3_IO_CH2 "2k" 6-0805_M 2126.54,1900 r180 top (schematic designator R3)
R3_OI_CH1 "2k" 6-0805_M 5613.46,6055 r0 top (schematic designator R3)
R3_OI_CH2 "2k" 6-0805_M 5613.46,5340 r0 top (schematic designator R3)
R3_OI_CH3 "2k" 6-0805_M 5612.83,3385 r0 top (schematic designator R3)
R3_OI_CH4 "2k" 6-0805_M 5613.46,2670 r0 top (schematic designator R3)
R4_IO_CH1 "39k" R1206 2755,4745 r0 top (schematic designator R4)
R4_IO_CH2 "39k" R1206 2755,2075 r0 top (schematic designator R4)
R4_OI_CH1 "39k" R1206 4985,5880 r180 top (schematic designator R4)
R4_OI_CH2 "39k" R1206 4985,5165 r180 top (schematic designator R4)
R4_OI_CH3 "39k" R1206 4984.37,3210 r180 top (schematic designator R4)
R4_OI_CH4 "39k" R1206 4985,2495 r180 top (schematic designator R4)
R5_IO_CH1 "680" 6-0805_M 3240,4600 r0 top (schematic designator R5)
R5_IO_CH2 "680" 6-0805_M 3240,1930 r0 top (schematic designator R5)
R5_OI_CH1 "680" 6-0805_M 4500,6025 r180 top (schematic designator R5)
R5_OI_CH2 "680" 6-0805_M 4500,5310 r180 top (schematic designator R5)
R5_OI_CH3 "680" 6-0805_M 4499.37,3355 r180 top (schematic designator R5)
R5_OI_CH4 "680" 6-0805_M 4500,2640 r180 top (schematic designator R5)
R6_IO_CH1 "10k" 6-0805_M 2126.54,4485 r180 top (schematic designator R6)
R6_IO_CH2 "10k" 6-0805_M 2126.54,1815 r180 top (schematic designator R6)
R6_OI_CH1 "10k" 6-0805_M 5613.46,6140 r0 top (schematic designator R6)
R6_OI_CH2 "10k" 6-0805_M 5613.46,5425 r0 top (schematic designator R6)
R6_OI_CH3 "10k" 6-0805_M 5612.83,3470 r0 top (schematic designator R6)
R6_OI_CH4 "10k" 6-0805_M 5613.46,2755 r0 top (schematic designator R6)
R7_IO_CH1 "10M" 6-0805_M 1900,4635 r0 top (schematic designator R7)
R7_IO_CH2 "10M" 6-0805_M 1900,1965 r0 top (schematic designator R7)
R7_OI_CH1 "10M" 6-0805_M 5840,5990 r180 top (schematic designator R7)
R7_OI_CH2 "10M" 6-0805_M 5840,5275 r180 top (schematic designator R7)
R7_OI_CH3 "10M" 6-0805_M 5839.37,3320 r180 top (schematic designator R7)
R7_OI_CH4 "10M" 6-0805_M 5840,2605 r180 top (schematic designator R7)
R8_IO_CH1 "47.5k" 6-0805_M 5261.54,4515 r90 top (schematic designator R8)
R8_IO_CH2 "47.5k" 6-0805_M 5261.54,1845 r90 top (schematic designator R8)
R8_OI_CH1 "47.5k" 6-0805_M 2475,6105 r270 top (schematic designator R8)
R8_OI_CH2 "47.5k" 6-0805_M 2475,5390 r270 top (schematic designator R8)
R8_OI_CH3 "47.5k" 6-0805_M 2474.37,3435 r270 top (schematic designator R8)
R8_OI_CH4 "47.5k" 6-0805_M 2475,2720 r270 top (schematic designator R8)
R9_IO_CH1 "RPot8" "POT SMD" 5570,4530 r180 top value=5k (schematic designator R9)
R9_IO_CH2 "RPot8" "POT SMD" 5570,1860 r180 top value=5k (schematic designator R9)
R9_OI_CH1 "RPot8" "POT SMD" 2170,6095 r0 top value=5k (schematic designator R9)
R9_OI_CH2 "RPot8" "POT SMD" 2170,5380 r0 top value=5k (schematic designator R9)
R9_OI_CH3 "RPot8" "POT SMD" 2169.37,3425 r0 top value=5k (schematic designator R9)
R9_OI_CH4 "RPot8" "POT SMD" 2170,2710 r0 top value=5k (schematic designator R9)
R10_IO_CH1 "39k" 6-0805_M 4586.54,4765 r0 top (schematic designator R10)
R10_IO_CH2 "39k" 6-0805_M 4586.54,2095 r0 top (schematic designator R10)
R10_OI_CH1 "39k" 6-0805_M 3153.46,5860 r180 top (schematic designator R10)
R10_OI_CH2 "39k" 6-0805_M 3153.46,5145 r180 top (schematic designator R10)
R10_OI_CH3 "39k" 6-0805_M 3152.83,3190 r180 top (schematic designator R10)
R10_OI_CH4 "39k" 6-0805_M 3153.46,2475 r180 top (schematic designator R10)
R11_IO_CH1 "9.31k" 6-0805_M 5265,4860 r90 top (schematic designator R11)
R11_IO_CH2 "9.31k" 6-0805_M 5265,2190 r90 top (schematic designator R11)
R11_OI_CH1 "9.31k" 6-0805_M 2475,5760 r270 top (schematic designator R11)
R11_OI_CH2 "9.31k" 6-0805_M 2475,5045 r270 top (schematic designator R11)
R11_OI_CH3 "9.31k" 6-0805_M 2474.37,3090 r270 top (schematic designator R11)
R11_OI_CH4 "9.31k" 6-0805_M 2475,2375 r270 top (schematic designator R11)
R12_IO_CH1 "10k" 6-0805_M 6095,4810 r180 top (schematic designator R12)
R12_IO_CH2 "10k" 6-0805_M 6095,2140 r180 top (schematic designator R12)
R12_OI_CH1 "10k" 6-0805_M 1645,5815 r0 top (schematic designator R12)
R12_OI_CH2 "10k" 6-0805_M 1645,5100 r0 top (schematic designator R12)
R12_OI_CH3 "10k" 6-0805_M 1644.37,3145 r0 top (schematic designator R12)
R12_OI_CH4 "10k" 6-0805_M 1645,2430 r0 top (schematic designator R12)
R13_IO_CH1 "RPot8" "POT SMD" 5570,4875 r180 top value=1k (schematic designator R13)
R13_IO_CH2 "RPot8" "POT SMD" 5570,2205 r180 top value=1k (schematic designator R13)
R13_OI_CH1 "RPot8" "POT SMD" 2170,5750 r0 top value=1k (schematic designator R13)
R13_OI_CH2 "RPot8" "POT SMD" 2170,5035 r0 top value=1k (schematic designator R13)
R13_OI_CH3 "RPot8" "POT SMD" 2169.37,3080 r0 top value=1k (schematic designator R13)
R13_OI_CH4 "RPot8" "POT SMD" 2170,2365 r0 top value=1k (schematic designator R13)
R14_IO_CH1 "4.75k" 6-0805_M 4861.54,4530 r90 top (schematic designator R14)
R14_IO_CH2 "4.75k" 6-0805_M 4861.54,1860 r90 top (schematic designator R14)
R14_OI_CH1 "4.75k" 6-0805_M 2878.46,6095 r270 top (schematic designator R14)
R14_OI_CH2 "4.75k" 6-0805_M 2878.46,5380 r270 top (schematic designator R14)
R14_OI_CH3 "4.75k" 6-0805_M 2877.83,3425 r270 top (schematic designator R14)
R14_OI_CH4 "4.75k" 6-0805_M 2878.46,2710 r270 top (schematic designator R14)
R15_IO_CH1 "0" 6-0805_M 6375,4630 r90 top (schematic designator R15)
R15_IO_CH2 "0" 6-0805_M 6340,2010 r180 top (schematic designator R15)
R15_OI_CH1 "0" 6-0805_M 1400,5945 r0 top (schematic designator R15)
R15_OI_CH2 "0" 6-0805_M 1400,5230 r0 top (schematic designator R15)
R15_OI_CH3 "0" 6-0805_M 1364.37,3320 r270 top (schematic designator R15)
R15_OI_CH4 "0" 6-0805_M 1365,2605 r270 top (schematic designator R15)
R16_IO_CH1 "RPot8" "POT SMD" 5160,4530 r180 top value=500 (schematic designator R16)
R16_IO_CH2 "RPot8" "POT SMD" 5160,1860 r180 top value=500 (schematic designator R16)
R16_OI_CH1 "RPot8" "POT SMD" 2580,6095 r0 top value=500 (schematic designator R16)
R16_OI_CH2 "RPot8" "POT SMD" 2580,5380 r0 top value=500 (schematic designator R16)
R16_OI_CH3 "RPot8" "POT SMD" 2579.37,3425 r0 top value=500 (schematic designator R16)
R16_OI_CH4 "RPot8" "POT SMD" 2580,2710 r0 top value=500 (schematic designator R16)
R17_IO_CH1 "909" 6-0805_M 4861.54,4860 r270 top (schematic designator R17)
R17_IO_CH2 "909" 6-0805_M 4861.54,2190 r270 top (schematic designator R17)
R17_OI_CH1 "909" 6-0805_M 2878.46,5765 r90 top (schematic designator R17)
R17_OI_CH2 "909" 6-0805_M 2878.46,5050 r90 top (schematic designator R17)
R17_OI_CH3 "909" 6-0805_M 2877.83,3095 r90 top (schematic designator R17)
R17_OI_CH4 "909" 6-0805_M 2878.46,2380 r90 top (schematic designator R17)
R18_IO_CH1 "RPot8" "POT SMD" 5160,4875 r180 top value=200 (schematic designator R18)
R18_IO_CH2 "RPot8" "POT SMD" 5160,2205 r180 top value=200 (schematic designator R18)
R18_OI_CH1 "RPot8" "POT SMD" 2580,5750 r0 top value=200 (schematic designator R18)
R18_OI_CH2 "RPot8" "POT SMD" 2580,5035 r0 top value=200 (schematic designator R18)
R18_OI_CH3 "RPot8" "POT SMD" 2579.37,3080 r0 top value=200 (schematic designator R18)
R18_OI_CH4 "RPot8" "POT SMD" 2580,2365 r0 top value=200 (schematic designator R18)
R19_IO_CH1 "0" 6-0805_M 1790,4740 r180 top (schematic designator R19)
R19_IO_CH2 "0" 6-0805_M 1790,2195 r180 top (schematic designator R19)
R19_OI_CH1 "0" 6-0805_M 5950,5765 r0 top (schematic designator R19)
R19_OI_CH2 "0" 6-0805_M 5950,5050 r0 top (schematic designator R19)
R19_OI_CH3 "0" 6-0805_M 5950,3220 r0 top (schematic designator R19)
R19_OI_CH4 "0" 6-0805_M 5950,2505 r0 top (schematic designator R19)
R20_IO_CH1 "0" 6-0805_M 1790,4865 r180 top (schematic designator R20)
R20_IO_CH2 "0" 6-0805_M 1790,2065 r180 top (schematic designator R20)
R20_OI_CH1 "0" 6-0805_M 5950,5890 r0 top (schematic designator R20)
R20_OI_CH2 "0" 6-0805_M 5950,5175 r0 top (schematic designator R20)
R20_OI_CH3 "0" 6-0805_M 5950,3095 r0 top (schematic designator R20)
R20_OI_CH4 "0" 6-0805_M 5950,2380 r0 top (schematic designator R20)
R21_IO_CH1 "0" 6-0805_M 6295,4630 r90 top (schematic designator R21)
R21_IO_CH2 "0" 6-0805_M 6340,1925 r180 top (schematic designator R21)
R21_OI_CH1 "0" 6-0805_M 1400,6030 r0 top (schematic designator R21)
R21_OI_CH2 "0" 6-0805_M 1400,5315 r0 top (schematic designator R21)
R21_OI_CH3 "0" 6-0805_M 1439.37,3320 r270 top (schematic designator R21)
R21_OI_CH4 "0" 6-0805_M 1440,2605 r270 top (schematic designator R21)
"R27_Side A power supply and references" "1.5R" R1206 2305,4070 r180 top (schematic designator R27)
"R27_Side B power supply and references" "1.5R" R1206 5435,3885 r0 top (schematic designator R27)
"R28_Side A power supply and references" "1.5R" R1206 2305,3900 r180 top (schematic designator R28)
"R28_Side B power supply and references" "1.5R" R1206 5435,4055 r0 top (schematic designator R28)
TP1_IO_CH1 "Vero Eyelet Test Point" "TEST PT SMD" 1920,4790 r90 top (schematic designator TP1)
TP1_IO_CH2 "Vero Eyelet Test Point" "TEST PT SMD" 1920,2120 r90 top (schematic designator TP1)
TP1_OI_CH1 "Vero Eyelet Test Point" "TEST PT SMD" 5820,5835 r270 top (schematic designator TP1)
TP1_OI_CH2 "Vero Eyelet Test Point" "TEST PT SMD" 5820,5120 r270 top (schematic designator TP1)
TP1_OI_CH3 "Vero Eyelet Test Point" "TEST PT SMD" 5819.37,3165 r270 top (schematic designator TP1)
TP1_OI_CH4 "Vero Eyelet Test Point" "TEST PT SMD" 5820,2450 r270 top (schematic designator TP1)
TP2_IO_CH1 "Vero Eyelet Test Point" "TEST PT SMD" 2086.54,4355 r90 top (schematic designator TP2)
TP2_IO_CH2 "Vero Eyelet Test Point" "TEST PT SMD" 2086.54,1685 r90 top (schematic designator TP2)
TP2_OI_CH1 "Vero Eyelet Test Point" "TEST PT SMD" 5653.46,6270 r270 top (schematic designator TP2)
TP2_OI_CH2 "Vero Eyelet Test Point" "TEST PT SMD" 5653.46,5555 r270 top (schematic designator TP2)
TP2_OI_CH3 "Vero Eyelet Test Point" "TEST PT SMD" 5652.83,3600 r270 top (schematic designator TP2)
TP2_OI_CH4 "Vero Eyelet Test Point" "TEST PT SMD" 5653.46,2885 r270 top (schematic designator TP2)
TP3_IO_CH1 "Vero Eyelet Test Point" "TEST PT SMD" 2565,4745 r0 top (schematic designator TP3)
TP3_IO_CH2 "Vero Eyelet Test Point" "TEST PT SMD" 2565,2075 r0 top (schematic designator TP3)
TP3_OI_CH1 "Vero Eyelet Test Point" "TEST PT SMD" 5175,5880 r180 top (schematic designator TP3)
TP3_OI_CH2 "Vero Eyelet Test Point" "TEST PT SMD" 5175,5165 r180 top (schematic designator TP3)
TP3_OI_CH3 "Vero Eyelet Test Point" "TEST PT SMD" 5174.37,3210 r180 top (schematic designator TP3)
TP3_OI_CH4 "Vero Eyelet Test Point" "TEST PT SMD" 5175,2495 r180 top (schematic designator TP3)
TP4_IO_CH1 "Vero Eyelet Test Point" "TEST PT SMD" 4851.54,4695 r270 top (schematic designator TP4)
TP4_IO_CH2 "Vero Eyelet Test Point" "TEST PT SMD" 4851.54,2025 r270 top (schematic designator TP4)
TP4_OI_CH1 "Vero Eyelet Test Point" "TEST PT SMD" 2888.46,5930 r90 top (schematic designator TP4)
TP4_OI_CH2 "Vero Eyelet Test Point" "TEST PT SMD" 2888.46,5215 r90 top (schematic designator TP4)
TP4_OI_CH3 "Vero Eyelet Test Point" "TEST PT SMD" 2887.83,3260 r90 top (schematic designator TP4)
TP4_OI_CH4 "Vero Eyelet Test Point" "TEST PT SMD" 2888.46,2545 r90 top (schematic designator TP4)
TP5_IO_CH1 "Vero Eyelet Test Point" "TEST PT SMD" 6370,4805 r270 top (schematic designator TP5)
TP5_IO_CH2 "Vero Eyelet Test Point" "TEST PT SMD" 6370,2135 r270 top (schematic designator TP5)
TP5_OI_CH1 "Vero Eyelet Test Point" "TEST PT SMD" 1370,5820 r90 top (schematic designator TP5)
TP5_OI_CH2 "Vero Eyelet Test Point" "TEST PT SMD" 1370,5105 r90 top (schematic designator TP5)
TP5_OI_CH3 "Vero Eyelet Test Point" "TEST PT SMD" 1369.37,3150 r90 top (schematic designator TP5)
TP5_OI_CH4 "Vero Eyelet Test Point" "TEST PT SMD" 1370,2435 r90 top (schematic designator TP5)
"TP+_Side A power supply and references" "Vero Eyelet Test Point" "TEST PT SMD" 2925,4140 r0 top (schematic designator TP+)
"TP+_Side B power supply and references" "Vero Eyelet Test Point" "TEST PT SMD" 4815,3815 r180 top (schematic designator TP+)
"TP-_Side A power supply and references" "Vero Eyelet Test Point" "TEST PT SMD" 2925,3820 r0 top (schematic designator TP-)
"TP-_Side B power supply and references" "Vero Eyelet Test Point" "TEST PT SMD" 4815,4135 r180 top (schematic designator TP-)
"TPCOM_Side A power supply and references" "Vero Eyelet Test Point" PAD-110-52 2925,3980 r90 top (schematic designator TPCOM)
"TPCOM_Side B power supply and references" "Vero Eyelet Test Point" PAD-110-52 4815,3975 r270 top (schematic designator TPCOM)
U1_IO_CH1 "ADA4177-2" SO-G8 2126.54,4720 r0 top (schematic designator U1)
U1_IO_CH2 "ADA4177-2" SO-G8 2126.54,2050 r0 top (schematic designator U1)
U1_OI_CH1 "ADA4177-2" SO-G8 5613.46,5905 r180 top (schematic designator U1)
U1_OI_CH2 "ADA4177-2" SO-G8 5613.46,5190 r180 top (schematic designator U1)
U1_OI_CH3 "ADA4177-2" SO-G8 5612.83,3235 r180 top (schematic designator U1)
U1_OI_CH4 "ADA4177-2" SO-G8 5613.46,2520 r180 top (schematic designator U1)
U2_IO_CH1 "ADA4625" SO-G8 3016.54,4625 r0 top (schematic designator U2)
U2_IO_CH2 "ADA4625" SO-G8 3016.54,1955 r0 top (schematic designator U2)
U2_OI_CH1 "ADA4625" SO-G8 4723.46,6000 r180 top (schematic designator U2)
U2_OI_CH2 "ADA4625" SO-G8 4723.46,5285 r180 top (schematic designator U2)
U2_OI_CH3 "ADA4625" SO-G8 4722.83,3330 r180 top (schematic designator U2)
U2_OI_CH4 "ADA4625" SO-G8 4723.46,2615 r180 top (schematic designator U2)
U3_IO_CH1 "HCNR201" DIP-8GW 3871.54,4675 r0 top (schematic designator U3)
U3_IO_CH2 "HCNR201" DIP-8GW 3871.54,2005 r0 top (schematic designator U3)
U3_OI_CH1 "HCNR201" DIP-8GW 3868.46,5950 r180 top (schematic designator U3)
U3_OI_CH2 "HCNR201" DIP-8GW 3868.46,5235 r180 top (schematic designator U3)
U3_OI_CH3 "HCNR201" DIP-8GW 3867.83,3280 r180 top (schematic designator U3)
U3_OI_CH4 "HCNR201" DIP-8GW 3868.46,2565 r180 top (schematic designator U3)
U4_IO_CH1 "ADA4625" SO-G8 4586.54,4600 r0 top (schematic designator U4)
U4_IO_CH2 "ADA4625" SO-G8 4586.54,1930 r0 top (schematic designator U4)
U4_OI_CH1 "ADA4625" SO-G8 3153.46,6025 r180 top (schematic designator U4)
U4_OI_CH2 "ADA4625" SO-G8 3153.46,5310 r180 top (schematic designator U4)
U4_OI_CH3 "ADA4625" SO-G8 3152.83,3355 r180 top (schematic designator U4)
U4_OI_CH4 "ADA4625" SO-G8 3153.46,2640 r180 top (schematic designator U4)
U5_IO_CH1 "ADA4177-1" SO-G8 6100,4655 r0 top (schematic designator U5)
U5_IO_CH2 "ADA4177-1" SO-G8 6100,1985 r0 top (schematic designator U5)
U5_OI_CH1 "ADA4177-1" SO-G8 1640,5970 r180 top (schematic designator U5)
U5_OI_CH2 "ADA4177-1" SO-G8 1640,5255 r180 top (schematic designator U5)
U5_OI_CH3 "ADA4177-1" SO-G8 1639.37,3300 r180 top (schematic designator U5)
U5_OI_CH4 "ADA4177-1" SO-G8 1640,2585 r180 top (schematic designator U5)
"U6_Side A power supply and references" "LT1021B-10" SO-G8 3160,4075 r0 top (schematic designator U6)
"U6_Side B power supply and references" "LT1021B-10" SO-G8 4575,3880 r180 top (schematic designator U6)

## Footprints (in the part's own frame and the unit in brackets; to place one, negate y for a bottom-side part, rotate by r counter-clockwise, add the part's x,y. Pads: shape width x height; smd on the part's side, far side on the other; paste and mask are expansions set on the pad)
6-0805_M [mm] "Chip Resistor, Body 2.0x1.2mm, IPC Low Density"
  rect 1.4x1.5 smd: 1(-1,0) 2(1,0)
  silkscreen extent 0,-0.65 0,0.65, body extent -1.07,-0.7 1.07,0.7, height 0.7
CC3216 [mm]
  rect 1.2x1.8 smd: 1(-1.3,0) 2(1.3,0)
  silkscreen extent -2.17,-1.5 2.17,1.5
CC7343 [mm]
  rect 2x3 smd: 1(0,0) 2(6,0)
  silkscreen extent -2.1,-2.2 7.3,2.2
DIP-8GW [mil] "DIP-8 Gull Wing"
  rect 100x60 smd: 1(-222,150) 2(-222,50) 3(-222,-50) 4(-222,-150) 5(222,-150) 6(222,-50) 7(222,50) 8(222,150)
  silkscreen extent -223,-230 222,230
"HDR1X3 SMD" [mil] "3 pos header surface mount"
  rect 50x116 smd: 1(0,0) 2(100,-140) 3(200,0)
  silkscreen extent -50,-215 250,75
"HDR1X6 SMD" [mil] "6 pos header surface mount"
  rect 50x116 smd: 1(0,0) 2(100,-140) 3(200,0) 4(300,-140) 5(400,0) 6(500,-140)
  silkscreen extent -50,-215 550,75
"Jumper 1210" [mm]
  rect 1.6x2.7 smd: 1(-1,0) 2(1,0)
"Mtg_Hole_M4 no silk" [mil] "Mounting Hole 4mm no silk"
  round 315 hole 157: 1(0,0)
PAD-110-52 [mil] "Pad 100mil Diameter 52mil Hole"
  round 110 hole 52: 1(0,0)
  silkscreen extent -66,-66 66,66
"POT SMD" [mm] "Potentiometer Surface Mount"
  rect 1x3 smd: 1(0,0) 2(2.54,4.5) 3(5.08,0)
  silkscreen extent -1.27,-1.91 6.35,6.4
R1206 [mm]
  rect 1.6x1.8 smd: 1(-1.4,0) 2(1.4,0)
  silkscreen extent -2.5,-1.2 2.5,1.2, body extent -1.6,-0.8 1.6,0.8, height 1
SMAJ [mil] "DO-214AC Diode package"
  rect 70x58 smd: 1(-80,0) 2(80,0)
  silkscreen extent -80,-70 110,70
SMB_Male_Vertical [mil] "Vertical Male SMB Connector"
  round 64.97 hole 43.31: 1(0,0)
  round 82.68 hole 55.12: 2(-100,-100) 2(-100,100) 2(100,-100) 2(100,100)
  silkscreen extent -135,-135 135,135
SO-G8 [mm] "SOIC, 8-Leads, Body 5.0x4.0mm (max), Pitch 1.27mm, IPC Medium Density"
  rect 2.2x0.6 smd: 1(-2.4,1.905) 2(-2.4,0.635) 3(-2.4,-0.635) 4(-2.4,-1.905) 5(2.4,-1.905) 6(2.4,-0.635) 7(2.4,0.635) 8(2.4,1.905)
  silkscreen extent -2.52,-2.5 0.9,2.88, body extent -3.01,-2.5 3.01,2.5, height 1.75
SOD-123 [mm]
  rect 0.7x1.2 smd: 1(-1.85,0) 2(1.85,0)
  silkscreen extent -2.5,-1.2 2.5,1.2, body extent -1.93,-0.81 1.93,0.89, height 1.44
"TEST PT SMD" [mm] "Test Point SMD Keystone 5015"
  rect 3.53x1.88 smd: 1(0,0)
"UBC Logo" [mil] "UBC Silkscreen Logo - 288mil x 392mil"
  silkscreen extent -146,-231 142,161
